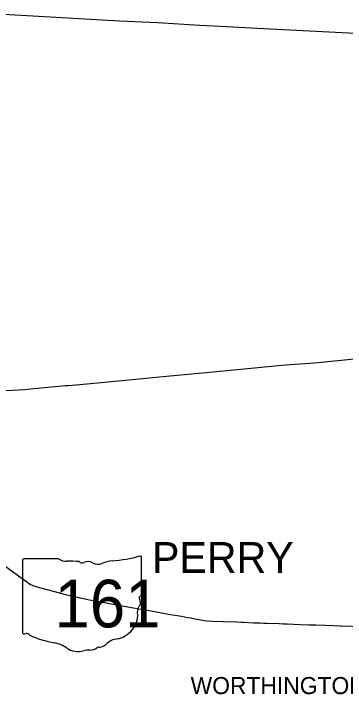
# Model space of a CAD drawing. Extents: x -1146 to -445, y -1283 to -822.
# Drawn here: x -944.21 to -919.93, y -945.99 to -896.21 of the extents above; entities that cross this region are included whole.
import ezdxf

# ---------------------------------------------------------------- set-up
doc = ezdxf.new("R2010")
doc.units = 0
for name, color, linetype in [('GM_X_Corporation_Text', 7, 'Continuous'), ('GM_X_County', 7, 'Continuous'), ('GM_X_Interstate_Route', 7, 'Continuous'), ('GM_X_State_Route', 7, 'Continuous'), ('GM_X_State_Shield', 7, 'Continuous'), ('GM_X_Township_Text', 7, 'Continuous')]:
    doc.layers.add(name, color=color, linetype=linetype)

msp = doc.modelspace()

# ---------------------------------------------------------------- linework, layer by layer
at = {"layer": 'GM_X_County'}
msp.add_lwpolyline([(-945.796, -896.215), (-936.46, -896.739), (-933.68, -896.859), (-930.577, -897.051), (-929.114, -897.139), (-925.424, -897.327), (-912.021, -898.019), (-911.931, -898.024), (-909.679, -898.071), (-909.589, -898.073), (-895.217, -898.76), (-895.141, -898.773), (-894.703, -898.8), (-892.494, -898.911), (-891.354, -898.969), (-891.291, -898.972), (-890.715, -899.002), (-890.494, -899.002), (-889, -899.078), (-887.326, -899.166)], dxfattribs=at)
at = {"layer": 'GM_X_Interstate_Route'}
for points in [[(-940.399, -923.41), (-940.223, -923.394), (-939.624, -923.343), (-936.767, -923.076), (-933.009, -922.725), (-929.327, -922.376), (-924.333, -921.901), (-922.171, -921.735), (-918.799, -921.407), (-915.089, -921.031), (-913.815, -920.965), (-913.08, -920.965), (-912.975, -920.974), (-911.473, -920.982), (-911.163, -920.988), (-910.435, -920.998)], [(-946.973, -923.787), (-945.002, -923.78), (-944.858, -923.775), (-944.296, -923.754), (-943.377, -923.687), (-942.964, -923.65)], [(-942.964, -923.65), (-942.719, -923.628), (-940.399, -923.41)]]:
    msp.add_lwpolyline(points, dxfattribs=at)
at = {"layer": 'GM_X_State_Route'}
for points in [[(-945.881, -935.84), (-944.853, -936.587), (-944.108, -937.123), (-943.24, -937.766), (-942.961, -937.945), (-942.848, -938.006), (-942.724, -938.062), (-942.49, -938.134), (-942.233, -938.206), (-941.213, -938.462), (-941.206, -938.464)], [(-941.206, -938.464), (-940.409, -938.674), (-939.428, -938.915), (-938.883, -939.026), (-938.657, -939.069), (-937.566, -939.265), (-937.323, -939.311)], [(-937.323, -939.311), (-936.674, -939.436), (-935.424, -939.66), (-934.898, -939.746), (-934.713, -939.779)], [(-934.713, -939.779), (-934.532, -939.812), (-933.744, -939.959), (-932.872, -940.113), (-931.934, -940.28), (-931.478, -940.361), (-931.244, -940.397), (-931.06, -940.431)], [(-931.06, -940.431), (-930.771, -940.484), (-930.092, -940.604), (-929.662, -940.627), (-928.874, -940.656), (-927.895, -940.688)], [(-927.895, -940.688), (-927.878, -940.688), (-927.498, -940.704)], [(-927.498, -940.704), (-927.394, -940.708), (-926.63, -940.747), (-926.174, -940.763)], [(-926.174, -940.763), (-925.888, -940.773), (-925.644, -940.782)], [(-925.644, -940.782), (-924.777, -940.812), (-924.451, -940.823), (-924.185, -940.836)], [(-924.185, -940.836), (-923.234, -940.881), (-922.585, -940.898)], [(-922.585, -940.898), (-922.574, -940.899), (-922.451, -940.903)], [(-922.451, -940.903), (-922.095, -940.914), (-921.394, -940.934), (-920.317, -940.976)], [(-920.317, -940.976), (-920.231, -940.979), (-919.456, -941.009), (-918.184, -941.075), (-917.119, -941.192), (-916.433, -941.283), (-913.888, -941.586), (-912.12, -941.674), (-911.653, -941.693)]]:
    msp.add_lwpolyline(points, dxfattribs=at)
at = {"layer": 'GM_X_State_Shield'}
for p, q in [((-943.547, -936.178), (-943.547, -941.461)), ((-940.913, -936.087), (-943.461, -936.087)), ((-934.846, -938.719), (-934.846, -935.956)), ((-934.847, -938.719), (-934.846, -938.719))]:
    msp.add_line(p, q, dxfattribs=at)
for centre, major_axis, start_param, end_param in [((-943.447, -936.166), (0.101, 0), 1.712693, 3.28349), ((-940.306, -935.473), (0.978, 0), 4.042523, 4.731795), ((-937.946, -928.884), (9.227, 0), 4.814394, 5.042369), ((-934.943, -935.944), (0.0969, 0), 6.141152, 7.989035), ((-939.982, -939.053), (3.51, 0), 1.404758, 1.657858), ((-939.185, -936.139), (0.282, 0), 3.836095, 5.185415), ((-938.771, -936.75), (0.586, 0), 0.950623, 2.079405), ((-938.014, -935.912), (0.705, 0), 4.081561, 5.145723), ((-936.769, -937.7), (1.856, 0), 1.699011, 2.107814), ((-934.868, -938.922), (0.15, 0), 1.883978, 3.671073), ((-935.822, -939.272), (0.9, 0), 5.934695, 6.695948), ((-934.949, -938.73), (0.104, 0), 5.05454, 6.418171), ((-934.499, -939.876), (0.655, 0), 2.387724, 3.262537), ((-937.429, -940.228), (2.308, 0), 5.101752, 6.440018), ((-943.447, -941.472), (0.102, 0), 3.00124, 4.508301), ((-943.431, -940.932), (0.776, 0), 4.665946, 4.897461), ((-943.272, -941.766), (0.28, 0), 0.519207, 1.627899), ((-939.739, -937.019), (6.663, 0), 4.195997, 4.488961), ((-936.455, -942.944), (1.264, 0), 1.647645, 2.488434), ((-941.726, -943.834), (2.085, 0), 0.823519, 1.323587), ((-939.471, -941.792), (1.323, 0), 4.026481, 4.996735), ((-938.61, -942.187), (0.705, 0), 4.691044, 5.507374), ((-937.972, -942.699), (0.198, 0), 1.147584, 2.315152), ((-938.057, -941.973), (0.746, 0), 4.937069, 5.64225), ((-938.707, -943.618), (1.087, 0), 1.495662, 1.94098)]:
    msp.add_ellipse(centre, major_axis=major_axis, ratio=0.8, start_param=start_param, end_param=end_param, dxfattribs=at)

# ---------------------------------------------------------------- texts
at = {"layer": 'GM_X_Corporation_Text'}
msp.add_text('WORTHINGTON', height=1.25, rotation=0, dxfattribs=at).set_placement((-931.254, -945.969))
at = {"layer": 'GM_X_State_Shield'}
msp.add_text('161', height=3.4805, dxfattribs=at).set_placement((-941.221, -941.088))
at = {"layer": 'GM_X_Township_Text'}
msp.add_text('PERRY', height=2.25, rotation=0, dxfattribs=at).set_placement((-934.08, -937.103))

doc.saveas('drawing.dxf')
